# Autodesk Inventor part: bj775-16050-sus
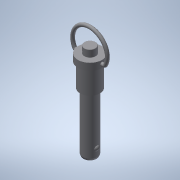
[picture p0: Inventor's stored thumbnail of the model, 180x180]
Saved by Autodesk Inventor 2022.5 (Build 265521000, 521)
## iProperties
Created: 2016-12
Part Number: bj775-16050-sus
Material: 一般
Document SubType Name: Modeling
Designer: imaocorp
Density: 1 g/cm^3
Appearance: 既定
Author: imaocorp
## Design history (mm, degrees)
node "bj775-16050-sus.x_t1"
node "bj775-16050-sus"
node "Base1"
